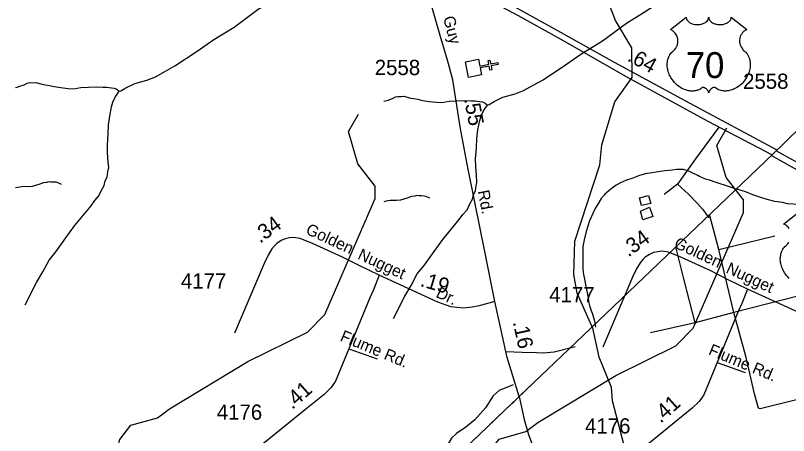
# Model space of a CAD drawing. Extents: x 2169602 to 2449496, y 721995 to 810662.
# Drawn here: x 2379098 to 2385429, y 762287 to 765731 of the extents above; entities that cross this region are included whole.
import ezdxf

# ---------------------------------------------------------------- set-up
doc = ezdxf.new("R2010")
doc.units = 0
doc.layers.add('Default', color=7, linetype='Continuous')

msp = doc.modelspace()

# ---------------------------------------------------------------- linework, layer by layer
at = {"layer": 'Default'}
for p, q in [((2384856.9, 763812.7), (2384782.4, 764098.2)), ((2384856.9, 763812.7), (2385315.4, 763923.9)), ((2384979.9, 763295.5), (2384856.9, 763812.7)), ((2385526.9, 763435.6), (2384979.9, 763295.5)), ((2384979.9, 763295.5), (2384663.4, 763210.5)), ((2384663.4, 763210.5), (2384298.1, 763127.3)), ((2381828.8, 762997.9), (2382058.7, 762915.2)), ((2384844.6, 762885.1), (2385074.5, 762802.3))]:
    msp.add_line(p, q, dxfattribs=at)
for points in [[(2383827.8, 763157.7), (2383696.8, 763454.3), (2383670.8, 763605.7), (2383677.8, 763881.1), (2383883.8, 764506.8), (2383899.8, 764670.4), (2384005.8, 765022.6), (2384146.7, 765223.1), (2384145.9, 765465.8), (2384011.8, 765688.4), (2383876.9, 766038.9), (2383441.7, 766503.7), (2383141.1, 766654.9)], [(2379948.7, 765109.2), (2379960.8, 765113.1), (2380002.7, 765137.3), (2380074.4, 765173.6), (2380175.2, 765200.7), (2380243.7, 765228.6), (2380327.2, 765273.6), (2380404.3, 765316.4), (2380586.3, 765438.5), (2380721.2, 765532.8), (2380890.3, 765635.6), (2381085.2, 765781.3), (2381230.8, 765869.2), (2382013, 766381.4)], [(2382964.6, 764996.3), (2382976.6, 765000.3), (2383018.5, 765024.4), (2383090.3, 765060.8), (2383191, 765087.9), (2383259.5, 765115.8), (2383343, 765160.7), (2383420.1, 765203.6), (2383602.1, 765325.7), (2383737, 765420), (2383906.2, 765522.8), (2384101, 765668.5), (2384246.6, 765756.3), (2385028.9, 766268.5)], [(2382401.7, 766169.2), (2382704.9, 766004.3), (2383213.4, 765728.9), (2383583.9, 765525.8), (2384094, 765232.6), (2384766.8, 764864), (2385293.7, 764587.2)], [(2379496.7, 759007.9), (2379504.1, 759015.1), (2380304.7, 759815.9), (2380643.2, 760139.7), (2382378.3, 761799.1), (2382962.7, 762357.9), (2383162.5, 762549.1), (2383203.7, 762588.6), (2383343.3, 762722.1), (2383397.7, 762774), (2383688.6, 763052.4), (2383809.2, 763167.6), (2385234.7, 764530.8), (2385310.2, 764603), (2385385.8, 764675.3), (2385550.5, 764839.9), (2385814.6, 765095.9), (2385991.4, 765267.1), (2386301.6, 765567.6), (2386380.1, 765643.5), (2386857.9, 766106.2)], [(2385334.7, 764626.5), (2384624, 765007.5), (2384002.4, 765345.7), (2383538.3, 765605.4), (2383105.1, 765846.2), (2382688.6, 766077.6)], [(2383023.2, 763386.5), (2382942.3, 763795.2), (2382859.6, 764199.4), (2382796.8, 764511.4), (2382739.3, 764817.2), (2382680.7, 765202.5), (2382636.7, 765363.8), (2382575, 765564.9), (2382492.8, 765849.4)], [(2379098.1, 765140), (2379110.9, 765143.5), (2379132.8, 765149.6), (2379170.7, 765161.6), (2379194.8, 765175.8), (2379214.6, 765179.9), (2379240.6, 765178), (2379264.7, 765182.1), (2379316.8, 765166.3), (2379340.7, 765162.4), (2379376.7, 765156.6), (2379414.7, 765146.9), (2379470.8, 765138.9), (2379530.8, 765131.3), (2379572.8, 765129.4), (2379632.8, 765139.8), (2379696.6, 765142.1), (2379760.7, 765146.2), (2379812.6, 765142.5), (2379846.6, 765142.7), (2379884.7, 765136.9), (2379906.7, 765135), (2379928.7, 765125), (2379948.7, 765109.2)], [(2379859.3, 764472.3), (2379861.5, 764481), (2379857.3, 764530.9), (2379853, 764604.8), (2379850.7, 764666.8), (2379856.4, 764758.9), (2379859.9, 764834.8), (2379869.8, 764904.8), (2379885.3, 764980.9), (2379895.1, 765020.9), (2379913, 765054.9), (2379924.9, 765077.1), (2379948.7, 765109.2)], [(2382114, 765027.2), (2382126.7, 765030.6), (2382148.7, 765036.8), (2382186.5, 765048.8), (2382210.6, 765062.9), (2382230.5, 765067.1), (2382256.4, 765065.2), (2382280.5, 765069.3), (2382332.6, 765053.4), (2382356.5, 765049.5), (2382392.6, 765043.8), (2382430.6, 765034), (2382486.6, 765026.1), (2382546.6, 765018.5), (2382588.6, 765016.6), (2382648.6, 765027), (2382712.4, 765029.3), (2382776.5, 765033.4), (2382828.4, 765029.7), (2382862.4, 765029.8), (2382900.5, 765024), (2382922.5, 765022.2), (2382944.5, 765012.1), (2382964.6, 764996.3)], [(2382875.2, 764359.5), (2382877.3, 764368.2), (2382873.1, 764418.1), (2382868.8, 764492), (2382866.5, 764554), (2382872.2, 764646.1), (2382875.7, 764722), (2382885.6, 764792), (2382901.1, 764868.1), (2382911, 764908), (2382928.8, 764942.1), (2382940.7, 764964.2), (2382964.6, 764996.3)], [(2381745.1, 763542.9), (2382043.7, 764229.4), (2382043.7, 764331.1), (2381900.8, 764514.4), (2381824.7, 764778.5), (2381907.8, 764921.1)], [(2379496.7, 759007.9), (2379504.1, 759015.1), (2379518.7, 759029.6), (2379537.1, 759048.1), (2380304.7, 759815.9), (2380643.2, 760139.7), (2381488.6, 760948.2), (2382962.7, 762357.8), (2382969.9, 762364.8), (2382982.2, 762376.6), (2383162.5, 762549.1), (2383178.5, 762564.2), (2383203.7, 762588.6), (2383229.1, 762612.9), (2383343.3, 762722), (2383397.7, 762774), (2383688.6, 763052.3), (2383809.2, 763167.6), (2385234.7, 764530.8), (2385310.2, 764603), (2385385.6, 764675.3), (2385550.5, 764839.9)], [(2379496.7, 759007.9), (2379504.1, 759015.1), (2379518.7, 759029.6), (2379537.1, 759048.1), (2380304.7, 759815.9), (2380643.2, 760139.7), (2381488.6, 760948.2), (2382962.7, 762357.8), (2382969.9, 762364.8), (2382982.2, 762376.6), (2383162.5, 762549.1), (2383178.5, 762564.2), (2383203.7, 762588.6), (2383229.1, 762612.9), (2383343.3, 762722), (2383397.7, 762774), (2383688.6, 763052.3), (2383809.2, 763167.6), (2385234.7, 764530.8), (2385310.2, 764603), (2385385.6, 764675.3), (2385550.5, 764839.9)], [(2384857.7, 764813.5), (2384668, 764554.2), (2384518.1, 764346.3)], [(2384761, 763430.1), (2385059.5, 764116.5), (2385059.5, 764218.2), (2384916.6, 764401.6), (2384840.5, 764665.6), (2384923.6, 764808.2)], [(2385287.9, 764581.7), (2385772.6, 764310.9), (2385930.6, 764223.4), (2386150.4, 764102.4)], [(2386153.7, 764163.9), (2385948.2, 764271), (2385803.8, 764355.7), (2385327.7, 764619.7)], [(2379178.6, 763358.3), (2379271.7, 763542.6), (2379321.3, 763628.8), (2379372.9, 763725.1), (2379428.7, 763793.3), (2379510.2, 763907.7), (2379581.6, 764005.8), (2379716.9, 764170.4), (2379746.8, 764212.6), (2379780.6, 764250.7), (2379800.4, 764292.7), (2379824.1, 764336.8), (2379833.9, 764374.8), (2379849.9, 764404.9), (2379853.6, 764449), (2379859.3, 764472.3)], [(2385015.4, 764302.5), (2385008.6, 764304.7), (2384938.2, 764328.8), (2384836.3, 764360), (2384780.5, 764379.8), (2384748.1, 764389.6), (2384698.1, 764411.3), (2384686, 764417.6), (2384646, 764437.4), (2384628, 764447), (2384603.8, 764457.2), (2384569.7, 764466.8), (2384541.9, 764468.6), (2384511.9, 764466.7), (2384475.8, 764462.4), (2384416.2, 764458), (2384309.7, 764439.7), (2384256, 764431.5), (2384208.2, 764419.3), (2384152.3, 764397), (2384102.4, 764378.9), (2384052.8, 764358.9), (2384016.5, 764338.4), (2383984.5, 764314.4), (2383956.6, 764292.3), (2383925.3, 764264.2)], [(2379476, 764344.7), (2379452, 764356.4), (2379430.1, 764362.6), (2379406.1, 764364.6), (2379386.2, 764364.3), (2379367.8, 764366.3), (2379351.8, 764362.2), (2379328.2, 764358.1), (2379318.2, 764355.9), (2379290.1, 764346), (2379236.3, 764329.4), (2379202.1, 764325.2), (2379170.1, 764327.2), (2379150.2, 764325.4), (2379118.4, 764320.9), (2379098.1, 764316.7)], [(2382194.4, 763245.5), (2382287.6, 763429.7), (2382337.1, 763515.9), (2382388.7, 763612.3), (2382444.5, 763680.5), (2382526, 763794.8), (2382597.4, 763893), (2382732.8, 764057.6), (2382762.6, 764099.8), (2382796.4, 764137.9), (2382816.3, 764179.9), (2382840, 764224), (2382849.7, 764262), (2382865.8, 764292), (2382869.5, 764336.2), (2382875.2, 764359.5)], [(2384518.1, 764346.3), (2384411.1, 764262.8)], [(2384518.1, 764346.3), (2384610.2, 764264.9), (2384683, 764190), (2384723.7, 764142.8), (2384749.4, 764108.5), (2384777.1, 764071.8)], [(2385821.4, 764064.5), (2385791.4, 764070.3), (2385759, 764080), (2385735.1, 764094.2), (2385674.8, 764125.7), (2385634.8, 764145.5), (2385608.7, 764159.6), (2385584.5, 764165.7), (2385521, 764178.9), (2385468.7, 764184.8), (2385420.7, 764186.8), (2385378.9, 764196.4), (2385316.7, 764206.2), (2385252.8, 764221.9), (2385192.7, 764239.5), (2385136.5, 764259.4), (2385084.4, 764281), (2385015.3, 764302.4)], [(2382491.9, 764231.8), (2382467.9, 764243.6), (2382445.9, 764249.7), (2382421.9, 764251.7), (2382402.1, 764251.5), (2382383.6, 764253.5), (2382367.6, 764249.4), (2382344, 764245.3), (2382334, 764243.1), (2382305.9, 764233.2), (2382252.2, 764216.6), (2382217.9, 764212.4), (2382185.9, 764214.4), (2382166, 764212.6), (2382134.3, 764208), (2382114, 764203.8)], [(2383925.3, 764264.2), (2383919.1, 764258.2), (2383895.3, 764230.1), (2383865.6, 764184), (2383847.8, 764153.8), (2383825.6, 764107.7), (2383798.1, 764047.7), (2383784, 764003.6), (2383770.2, 763959.5), (2383754.2, 763891.7), (2383745, 763835.5), (2383743.2, 763793.6), (2383743.6, 763737.6), (2383743.6, 763651.6), (2383749.9, 763607.7), (2383754.2, 763581.9), (2383766.1, 763523.6), (2383782.7, 763441.7), (2383786.9, 763417.9), (2383790.7, 763385.7), (2383799.2, 763354), (2383802.8, 763336), (2383808.8, 763318.1)], [(2384280.8, 764255.8), (2384301.3, 764189.8), (2384223.2, 764173.2), (2384206.8, 764235.4), (2384280.8, 764255.8)], [(2384291.1, 764159.8), (2384317.7, 764081.9), (2384235.7, 764053.7), (2384215.6, 764127.4), (2384291.1, 764159.8)], [(2385432.8, 763984.2), (2385427.3, 763992), (2385421.6, 763998.4), (2385415.9, 764004.1), (2385410.5, 764008.4), (2385405.3, 764012.1), (2385398.7, 764016.1), (2385392.4, 764019.2), (2385388.5, 764020.8), (2385517.1, 764123.2)], [(2382076.3, 763600.4), (2381918.7, 763677.2), (2381775.1, 763748.9), (2381531.3, 763860.8), (2381429.2, 763902.1), (2381394.2, 763908.4), (2381374.4, 763909.8), (2381341.3, 763906.8), (2381307.6, 763899.5), (2381273.4, 763884.5), (2381239.3, 763861.1), (2381218.7, 763843.2), (2381196.6, 763816.3), (2381166.7, 763765.1), (2381134, 763697.2), (2380891, 763124.6)], [(2384663.4, 763210.5), (2384571.2, 763572.2), (2384505.2, 763833.2)], [(2385434.2, 763574), (2385422, 763586.4), (2385414.8, 763594.6), (2385403.5, 763609.1), (2385396.3, 763619.7), (2385391.6, 763627.5), (2385384.8, 763639.9), (2385381, 763647.7), (2385376.2, 763659.1), (2385372.3, 763669.6), (2385369.1, 763679.4), (2385367.4, 763685.7), (2385365, 763696.8), (2385363.5, 763704.6), (2385362.1, 763715.3), (2385361.3, 763726.6), (2385361.1, 763737), (2385361.4, 763745.7), (2385362.4, 763755.8), (2385364.1, 763766.5), (2385366.1, 763775.7), (2385368, 763782.3), (2385370.7, 763790.4), (2385374.4, 763799.3), (2385378.6, 763807.8), (2385382.7, 763814.8), (2385387.8, 763822.4), (2385392.8, 763828.9), (2385399.3, 763836), (2385406.2, 763842.6), (2385412.4, 763847.7), (2385419.9, 763855), (2385423.8, 763859.4), (2385428.4, 763865.5), (2385432.1, 763871.2)], [(2385092.2, 763487.5), (2384934.6, 763564.3), (2384790.9, 763636.1), (2384547.2, 763747.9), (2384445.1, 763789.3), (2384410, 763795.6), (2384390.2, 763796.9), (2384357.2, 763794), (2384323.4, 763786.6), (2384289.2, 763771.7), (2384255.1, 763748.3), (2384234.6, 763730.4), (2384212.4, 763703.5), (2384182.5, 763652.3), (2384149.8, 763584.3), (2383906.9, 763011.7)], [(2382076.3, 763600.4), (2382030.2, 763481.6), (2382001, 763416.8), (2381719.5, 762732), (2381680.7, 762678), (2381624.9, 762624), (2381475.2, 762503.9), (2381029, 762138.6), (2380972.7, 762084.6), (2380945.6, 762044.1), (2380920.8, 761983.3), (2380871, 761855)], [(2383023.2, 763386.5), (2382896, 763349.8), (2382837.3, 763338.1), (2382769.3, 763331), (2382712.9, 763335.7), (2382663.6, 763342.7), (2382558, 763380.3), (2382076.3, 763600.4)], [(2379098.1, 760117.3), (2379649.7, 761020.8), (2379773.8, 761362.7), (2379846.8, 761830.4), (2379952.8, 762254.6), (2380043.8, 762370.8), (2380260.8, 762432), (2380359.8, 762505.4), (2380999.8, 762892.6), (2381490.7, 763135.2), (2381630.7, 763279.9), (2381745.1, 763542.9)], [(2385092.2, 763487.5), (2385046, 763368.8), (2385016.9, 763304), (2384735.3, 762619.2), (2384696.5, 762565.2), (2384640.7, 762511.2), (2384491, 762391.1), (2384044.8, 762025.8), (2383988.5, 761971.8), (2383961.4, 761931.3), (2383936.7, 761870.5), (2383886.8, 761742.2)], [(2386039, 763273.7), (2385911.9, 763237), (2385853.2, 763225.2), (2385785.1, 763218.2), (2385728.8, 763222.9), (2385679.5, 763229.9), (2385573.8, 763267.5), (2385092.2, 763487.5)], [(2382114, 760004.5), (2382665.5, 760908), (2382789.6, 761249.9), (2382862.6, 761717.5), (2382968.6, 762141.8), (2383059.7, 762258), (2383276.6, 762319.2), (2383375.6, 762392.6), (2384015.6, 762779.8), (2384506.5, 763022.4), (2384646.6, 763167), (2384761, 763430.1)], [(2383223.2, 762607.2), (2383123.8, 762926.1), (2383023.2, 763386.5)], [(2383808.8, 763318.1), (2383819.5, 763290.1), (2383825.4, 763274.2), (2383837.7, 763236.2), (2383841.6, 763214.1), (2383847.1, 763176.4)], [(2385516.1, 762585.7), (2385196, 762506.1), (2385181.5, 762511.5), (2385149, 762629.1), (2385080.3, 762925.7), (2384979.9, 763295.5)], [(2387673.2, 761241.7), (2387233.6, 761036.2), (2386975.6, 761002.1), (2386533.5, 761076.8), (2385883.5, 761257.3), (2385357.6, 761471.4), (2385040.5, 761569.8), (2384648.7, 761574.5), (2384548.6, 761609.3), (2384356.7, 761741.2), (2384231.6, 761881.5), (2384113.7, 762090.6), (2383986.6, 762572.2), (2383977.6, 762680.6), (2383876.7, 762928.7), (2383823, 763180.3)], [(2383113.2, 762974.6), (2383248.4, 762969.2), (2383364, 762967.1), (2383423.2, 762964.7), (2383509.5, 762972.2), (2383680.1, 763015.4)], [(2383172.7, 762701.5), (2383057.8, 762656), (2383010.7, 762611), (2382946.5, 762514.6), (2382860.9, 762416), (2382785.9, 762356.1), (2382708.8, 762304.6), (2382668.1, 762263.9), (2382638.2, 762212.5), (2382616.8, 762158.9), (2382591.1, 762099), (2382556.8, 762028.3)], [(2383223.2, 762607.2), (2383262.5, 762418.6), (2383297.9, 762296.1), (2383336.3, 762191.2), (2383373.2, 762120.3), (2383447.1, 762005.1), (2383528.3, 761882.6), (2383602.1, 761780.7), (2383689.3, 761681.7), (2383859.1, 761517.8), (2384133.8, 761266.7), (2384313.9, 761111.7), (2384575.3, 760869.5), (2384711.2, 760741), (2384863.3, 760599.2), (2384947.5, 760506.2), (2385033.1, 760410.2), (2385310.7, 760060.2), (2385536.1, 759749.8), (2385617.4, 759650.9), (2385714.1, 759546.6)]]:
    msp.add_lwpolyline(points, dxfattribs=at)
for points in [[(2384591, 765716.5), (2384591.3, 765711.2), (2384592.6, 765704.9), (2384593.6, 765701.6), (2384596.5, 765695.4), (2384601.4, 765688), (2384608.2, 765680.8), (2384615.9, 765674.5), (2384621, 765671.2), (2384629.8, 765666.5), (2384639.7, 765662.3), (2384650.8, 765659.1), (2384662.2, 765656.8), (2384674.5, 765655.4), (2384686.8, 765655.2), (2384700, 765656.2), (2384714.6, 765659), (2384721.3, 765660.8), (2384728.8, 765663.3), (2384735.8, 765666.2), (2384743.5, 765670.3), (2384749.6, 765674.3), (2384754.5, 765677.8), (2384761.3, 765684.3), (2384766.7, 765691.1), (2384769, 765694.9), (2384771, 765698.5), (2384773.7, 765706.3), (2384774.4, 765709.7), (2384775, 765716.8), (2384775.4, 765710.8), (2384776, 765707.1), (2384777, 765703.5), (2384778.5, 765699.6), (2384781.3, 765694.1), (2384784.3, 765689.6), (2384790, 765682.8), (2384793.6, 765679.4), (2384796.9, 765676.8), (2384805.6, 765670.8), (2384815.8, 765665.6), (2384820.8, 765663.4), (2384826, 765661.6), (2384832.5, 765659.6), (2384839.3, 765658), (2384846, 765656.9), (2384852.8, 765655.9), (2384859.8, 765655.4), (2384865.5, 765655.2), (2384872.5, 765655.3), (2384878.9, 765655.7), (2384885.6, 765656.4), (2384892.8, 765657.6), (2384898.7, 765658.9), (2384906.4, 765661), (2384913.4, 765663.5), (2384919.6, 765666.1), (2384927.6, 765670.3), (2384934, 765674.4), (2384938.7, 765678.2), (2384944.3, 765683.3), (2384949.7, 765689.5), (2384952.8, 765694), (2384955, 765698.6), (2384957, 765703.5), (2384958.3, 765708.6), (2384958.9, 765713.1), (2384959, 765716.9), (2385087.6, 765614.5), (2385084.6, 765613.3), (2385077.6, 765609.9), (2385072, 765606.6), (2385063.2, 765600.4), (2385059.4, 765597), (2385055.6, 765593.4), (2385052.1, 765589.6), (2385049, 765586.1), (2385045.3, 765580.9), (2385042, 765575.7), (2385038.7, 765570), (2385036.3, 765565.1), (2385032.4, 765554.7), (2385030.5, 765548.2), (2385029.2, 765542.7), (2385027.7, 765531.2), (2385027.3, 765525.7), (2385027.3, 765520.3), (2385027.7, 765514.6), (2385028.2, 765509.2), (2385029.2, 765503.5), (2385030.1, 765498.4), (2385031.7, 765492.3), (2385034, 765485.1), (2385036.8, 765478.2), (2385042.6, 765467.1), (2385050.2, 765455.7), (2385055.6, 765449.3), (2385060.9, 765443.8), (2385068.9, 765437.1), (2385073.1, 765433.3), (2385078.1, 765428.4), (2385086.1, 765419), (2385089.4, 765414.6), (2385092.7, 765409.7), (2385095.7, 765404.6), (2385098.8, 765399.1), (2385101.2, 765394.3), (2385105.7, 765383.3), (2385109, 765372.6), (2385110.5, 765367), (2385112.9, 765354.4), (2385113.9, 765348.1), (2385114.8, 765335.8), (2385114.9, 765320.9), (2385113.7, 765306.8), (2385111.1, 765290.3), (2385108.9, 765280.4), (2385105.5, 765269), (2385102.2, 765259), (2385096.3, 765244.3), (2385091.1, 765233.7), (2385084.4, 765221.2), (2385079.8, 765213.7), (2385074.4, 765205.7), (2385067.6, 765196.4), (2385059.7, 765186.5), (2385050.2, 765176.1), (2385042.5, 765168.4), (2385032.5, 765159.5), (2385026.4, 765154.4), (2385017.8, 765147.9), (2385005.9, 765140), (2384994.2, 765133.2), (2384984.3, 765128.2), (2384975.5, 765124.4), (2384964.1, 765120), (2384945.1, 765114.8), (2384938.2, 765113.3), (2384930, 765112.1), (2384922.3, 765111.4), (2384914.9, 765110.9), (2384904.8, 765110.9), (2384894.9, 765111.7), (2384885.5, 765113), (2384875.7, 765115.1), (2384865.4, 765118.1), (2384856.1, 765121.8), (2384846.7, 765126.4), (2384830.8, 765136.4), (2384826.2, 765138.9), (2384823.6, 765139.6), (2384817.5, 765139.9), (2384811.7, 765138.6), (2384805.8, 765136.3), (2384802.2, 765134.4), (2384797.5, 765131.3), (2384793.8, 765128.4), (2384789.4, 765124.2), (2384786.4, 765120.7), (2384784, 765118), (2384779.6, 765110.9), (2384778, 765107.6), (2384776.3, 765103.2), (2384774.8, 765096.9), (2384772.8, 765104.9), (2384770.5, 765110.2), (2384767.7, 765114.8), (2384764.9, 765118.8), (2384760.4, 765124), (2384756.4, 765127.9), (2384751.5, 765131.8), (2384746.3, 765134.9), (2384742.2, 765137), (2384738.4, 765138.5), (2384733.8, 765139.6), (2384730, 765139.9), (2384726.9, 765139.9), (2384722.6, 765138.9), (2384716.8, 765134.7), (2384711.3, 765130.9), (2384705.3, 765127.2), (2384698.1, 765123.4), (2384692.9, 765120.9), (2384686.6, 765118.5), (2384679.4, 765116.1), (2384671.5, 765114), (2384663.3, 765112.4), (2384656.2, 765111.3), (2384648.5, 765110.6), (2384641.6, 765110.4), (2384634.4, 765110.5), (2384627.6, 765111), (2384619.8, 765111.7), (2384610.1, 765113.1), (2384602, 765114.9), (2384593.5, 765117.2), (2384584.8, 765120), (2384575.5, 765123.5), (2384563.8, 765128.6), (2384555.6, 765132.8), (2384542.8, 765140.2), (2384527.8, 765150.6), (2384516.4, 765159.8), (2384508.1, 765167.3), (2384495.9, 765179.8), (2384488.7, 765187.9), (2384477.4, 765202.5), (2384470.2, 765213), (2384465.5, 765220.8), (2384458.7, 765233.2), (2384454.9, 765241.1), (2384450.1, 765252.5), (2384446.2, 765262.9), (2384443.1, 765272.8), (2384441.3, 765279.1), (2384438.9, 765290.1), (2384437.4, 765297.9), (2384436, 765308.6), (2384435.2, 765319.9), (2384435, 765330.4), (2384435.3, 765339), (2384436.3, 765349.1), (2384438, 765359.8), (2384440.1, 765369), (2384441.9, 765375.6), (2384444.6, 765383.7), (2384448.3, 765392.6), (2384452.5, 765401.1), (2384456.6, 765408.2), (2384461.7, 765415.8), (2384466.7, 765422.2), (2384473.2, 765429.4), (2384480.1, 765435.9), (2384486.3, 765441), (2384493.8, 765448.3), (2384497.7, 765452.7), (2384502.3, 765458.9), (2384506.1, 765464.5), (2384509, 765469.6), (2384512.9, 765477.2), (2384515.3, 765482.8), (2384518.2, 765491.4), (2384519.7, 765497.5), (2384521.2, 765505.4), (2384522.2, 765512.7), (2384522.6, 765521.9), (2384522.4, 765529.5), (2384521.4, 765538.4), (2384519.7, 765546.9), (2384517.7, 765554.4), (2384514.5, 765562.9), (2384511.6, 765569.1), (2384506.7, 765577.5), (2384501.2, 765585.4), (2384495.5, 765591.8), (2384489.8, 765597.5), (2384484.4, 765601.7), (2384479.2, 765605.4), (2384472.6, 765609.4), (2384466.3, 765612.5), (2384462.4, 765614.1)], [(2382888.6, 765371.4), (2382899.6, 765315.5), (2382974.3, 765330.1), (2382968.2, 765361.5), (2382983.9, 765364.6), (2382990, 765333.2), (2383049, 765344.7), (2383052.1, 765329), (2382993.1, 765317.5), (2382999.2, 765286.1), (2382983.6, 765283), (2382977.4, 765314.4), (2382902.7, 765299.8), (2382913.6, 765243.2), (2382809.2, 765222.8), (2382784.1, 765350.9)]]:
    msp.add_lwpolyline(points, close=True, dxfattribs=at)

# ---------------------------------------------------------------- texts
for s, height, rotation, p in [('Guy', 95, 284.55124, (2382599.2, 765713)), ('.64', 125, 331.44694, (2384101.2, 765363.1)), ('.55', 125, 280.65986, (2382770.9, 765045.8)), ('Rd.', 95, 281.03706, (2382882.9, 764290.1)), ('.34', 125, 36.02757, (2381100.6, 763858.3)), ('Golden', 95, 335.05656, (2381467.7, 763944.2)), ('.34', 125, 36.02757, (2384116.4, 763745.5)), ('Golden', 95, 335.05656, (2384483.5, 763831.3)), ('Nugget', 95, 335.05658, (2381893.5, 763738.2)), ('Nugget', 95, 335.05658, (2384909.3, 763625.4)), ('.19', 125, 343.62458, (2382405.9, 763512.7)), ('Dr.', 95, 335.05658, (2382534.1, 763424.7)), ('.16', 125, 282.32702, (2383169.7, 763216.3)), ('Flume Rd.', 95, 337.25608, (2381749.9, 763066.7)), ('Flume Rd.', 95, 337.25608, (2384765.8, 762953.9)), ('.41', 125, 41.83206, (2381364.7, 762495)), ('.41', 125, 41.83206, (2384380.5, 762382.2))]:
    msp.add_text(s, height=height, rotation=rotation, dxfattribs=at).set_placement(p)
for s, height, p in [('70', 212.5, (2384586.7, 765217.2)), ('2558', 125, (2382040.2, 765241.7)), ('2558', 125, (2385056.1, 765128.9)), ('4177', 125, (2380452.9, 763492)), ('4177', 125, (2383468.7, 763379.2)), ('4176', 125, (2380746.4, 762416.1)), ('4176', 125, (2383762.2, 762303.3))]:
    msp.add_text(s, height=height, dxfattribs=at).set_placement(p)

doc.saveas('drawing.dxf')
